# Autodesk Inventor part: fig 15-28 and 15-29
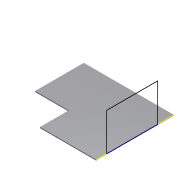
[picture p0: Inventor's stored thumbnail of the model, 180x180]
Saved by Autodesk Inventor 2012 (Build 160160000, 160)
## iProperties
Created: 2005-03
Part Number: fig 15-28 and 15-29
Document SubType Name: Sheet Metal
Designer: CADCIM
Manufacturer: Standard
Standards Organization: Custom
Density: 1 g/cm^3
Sheet Metal Rule: Default
Material: Default
Author: CADCIM
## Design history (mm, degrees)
node "Face1"
  sketch "Sketch1"
    geometry: L1 (29.25, 32.25)-(-19.875, 32.25); L2 (-19.875, 32.25)-(-19.875, 5.625); L3 (-19.875, 5.625)-(-1.5, 5.625); L4 (-1.5, 5.625)-(-1.5, -10.125); L5 (-1.5, -10.125)-(29.25, -10.125); L6 (29.25, -10.125)-(29.25, 32.25)
    constraints: 12 end point, 4 parallel, 1 horizontal, 1 perpendicular
sketch "Sketch2"
  geometry: L1 (-0.5, 42.375)-(-0.5, 0) reference; L2 (-0.5, 5.593)-(-21.049, 5.593); L3 (-21.049, 5.593)-(-21.049, 33.56); L4 (-21.049, 33.56)-(-0.5, 33.56); L5 (-0.5, 33.56)-(-0.5, 5.593)
  constraints: 8 end point, 2 parallel, 1 horizontal, 1 perpendicular, 1 point on line
body "Solid1"
face "Plate1" dims "Thickness" = 0.5
other parameters: "BendRadius" = 0.5 (= Thickness), "BendReliefWidth" = 0.5 (= Thickness), "BendReliefDepth" = 0.25 (= 0.5 x Thickness), "CornerReliefSize" = 2 (= 4 x Thickness), "SeamGap" = 0.01, "MinimumRemnant" = 1 (= 2 x Thickness), "TransitionRadius" = 0.5 (= BendRadius), "d0" = 0.5 (= BendRadius), "JacobiRadiusSize" = 0.5 (= Thickness), "GapSize" = 0.5 (= Thickness)
